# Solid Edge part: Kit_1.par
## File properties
Sűrűség: 0,000 kg/m^3
Pontosság: 0,990
Author: ahadarics
Last saved by: ahadarics
Revision: 77
Username: ahadarics
Dokumentum tartalom típus: 0
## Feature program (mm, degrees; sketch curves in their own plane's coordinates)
base feature "unnamed BaseFeature 1"
thread "unnamed Thread 1"
chamfer "unnamed Chamfer 1"
sketch for "Furat_1" plane through (0, -42.5, 8.5) normal (0, 0, 1) x-axis (0, 1, 0)
  hole centre (0.5, 0) bore radius 2.067
hole "Furat_1" nominal diameter 5 finite  ThreadDepth = 4.5 mm
chamfer "Letörés_2" setback 0.5
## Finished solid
Body 1: solid body, 48 faces, 53 edges, 8 vertices.
  Faces by surface: cylinder 15, plane 15, cone 11, torus 7
  Edges by curve: circle 45, line 6, intersection 2
Bounding box of the edges (mm; curved faces can reach further): 19.000 x 28.500 x 18.000, from (-9.5, -65, -9.5) to (9.5, -36.5, 8.5).
Cylindrical faces by radius (mm): R2.067 x2, R3.25 x3, R3.55 x1, R4.5 x1, R4.55 x1, R5.55 x1, R5.6 x1, R6.6 x1, R6.85 x1, R8 x2, R9.5 x1
Conical faces (half-angle, radius in mm at the cone's reference point): 8.8315 deg R4.75 x1, 15 deg R5.55 x1, 20.542 deg R3.55 x1, 24.3997 deg R3.55 x1, 27.3182 deg R3.0335 x1, 29.1112 deg R4.1553 x1, 45 deg R2.067 x1, 45 deg R4.65 x1, 45 deg R4.8 x1, 45 deg R8 x1, 60 deg R7.425 x1
Toroidal faces (ring radius, tube radius in mm): R3.2 r0.2 x1, R3.3 r0.3 x1, R4.3301 r0.2 x1, R4.35 r0.2 x1, R5.35 r0.2 x1, R5.4 r0.2 x2
Planar faces by outward normal: +y 5, +z 2, -y 8
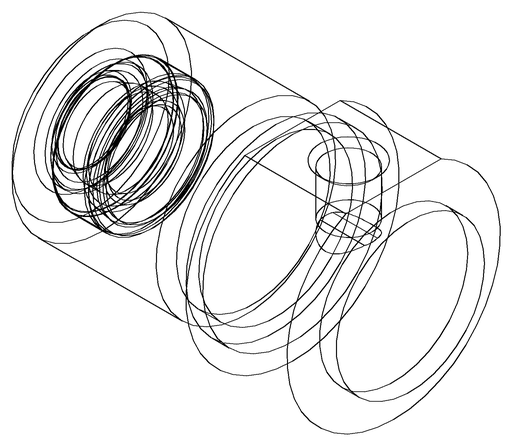
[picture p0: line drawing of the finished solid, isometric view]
